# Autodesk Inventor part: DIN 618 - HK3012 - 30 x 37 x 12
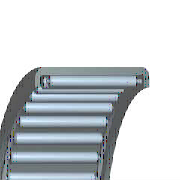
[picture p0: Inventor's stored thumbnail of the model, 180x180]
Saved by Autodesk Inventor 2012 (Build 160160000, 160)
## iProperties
Created: 2011-02
Part Number: DIN 618 - HK3012 - 30 x 37 x 12
Material: Steel, Mild
Description: Needle Roller Bearing Drawn Cup
Document SubType Name: Modeling
Standard: DIN 618
Designer: Admin
Standards Organization: DIN
Language: en-US
Size Designation: HK3012 - 30 x 37 x 12
Categories: <MemberInstance><Categories><Category DisplayName="Shaft Parts" InternalName="7f7aeb1f-a693-4053-b835-cee3144e0d98" Mnemonic="SHFT"><Category DisplayName="Beari
Density: 1 g/cm^3
IsCustomPart: 0
Author: Admin
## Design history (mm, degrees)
revolve "Body" stored, may be unused: angle "d43" = 90 deg
revolve "Groove" stored, may be unused: angle "d44" = 90 deg
revolve "Roller" stored, may be unused: angle "d48" = 90 deg
pattern_circular "Grooves" dims angle "d4" = 360 deg
body "Solid1"
sketch "Sketch"
  geometry: L1 (6, 16.312)-(6, 15.875); L2 (0.875, 17.625)-(0.875, 15); L3 (0.875, 15)-(0, 15); L4 (0, 18.5)-(12, 18.5); L5 (1.531, 16.75)-(1.531, 15.875); L6 (11.125, 17.625)-(11.125, 15); L7 (11.125, 15)-(12, 15); L8 (12, 15)-(12, 18.5); L9 (10.469, 16.75)-(10.469, 15.875); L10 (0.875, 17.625)-(11.125, 17.625); L11 (2.713, 16.312)-(2.713, 17.888); L12 (9.288, 17.888)-(9.288, 16.312); L13 (2.713, 17.888)-(9.288, 17.888); L14 (1.531, 16.75)-(10.469, 16.75); L15 (1.531, 15.875)-(10.469, 15.875); L16 (1.531, 16.312)-(10.469, 16.312); L17 (3.527, 15)-(8.473, 15); L18 (-2.4, 0)-(14.4, 0) reference; L19 (0, -0.154)-(0, 4.109) reference; A1 r 1.838 centre (4.813, 16.312) between (3.527, 17.625) and (2.975, 16.312); A2 r 1.838 centre (7.188, 16.312) between (9.025, 16.312) and (8.473, 17.625); A3 r 1.838 centre (4.813, 16.312) between (2.975, 16.312) and (3.527, 15); A4 r 1.838 centre (7.188, 16.312) between (8.473, 15) and (9.025, 16.312)
  constraints: 34 end point, 9 point on line, 8 point on circle, 5 symmetric about line, 4 centre point, 4 midpoint, 2 collinear, 1 parallel, 1 perpendicular, 7 other
  dimensions: "d0" = 1.8375 radius of A3 (= -0.7 x YM - 0.35 x WD + 0.35 x BD); "d8" = 30 diameter of L17 L18 (= WD); "d9" = 35.25 diameter of L10 L18 (= BD - 2 x YM); "d10" = 37 diameter of L4 L18 (= BD); "d11" = 33.5 diameter of L14 L18 (= -1.33333 x YM + 0.666667 x BD + 0.333333 x WD); "d12" = 35.775 diameter of L13 L18 (= -2.2 x YM + 1.1 x BD - 0.1 x WD); "d13" = 0.875 distance between parallel lines of L19 L2 (= YM); "d14" = 2.7125 distance between parallel lines of L19 L11 (= 0.35 x BD - 0.35 x WD + 0.3 x YM); "d15" = 1.53125 distance between parallel lines of L19 L5 (= 0.75 x YM + 0.125 x BD - 0.125 x WD); "d16" = 4.8125 distance from line of A1.centre L19 (= -0.5 x YM - 0.75 x WD + 0.75 x BD); "d17" = 12 distance between parallel lines of L19 L8 (= KB); "d18" = 6 distance from line of L19 L1.start (= 0.5 x KB)
fillet "Fillet1" dims "d1" = 0.65625 (= -0.25 x YM - 0.125 x WD + 0.125 x BD), "d2" = 1.53125 (= 0.125 x BD - 0.125 x WD + 0.75 x YM)
other parameters: "WD" = 30 [user parameter; used in 11 equation terms], "BD" = 37 [user parameter; used in 12 equation terms], "KB" = 12 [user parameter; used in 2 equation terms], "YM" = 0.875 [user parameter; used in 11 equation terms], "d5" = 0, "d6" = 0, "d7" = 0, "d69" = 0, "d70" = 0, "BC0" = 1.83e+07 [user parameter], "BBA" = 0 [user parameter], "KRS" = 0.8 [user parameter], "BC" = 1.16e+07 [user parameter], "BR" = 18.5 (= 0.5 x BD) [user parameter], "WR" = 15 (= 0.5 x WD) [user parameter]
